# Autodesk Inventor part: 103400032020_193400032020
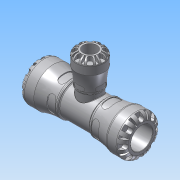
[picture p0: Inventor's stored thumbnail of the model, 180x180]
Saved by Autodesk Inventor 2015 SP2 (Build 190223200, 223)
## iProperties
Created: 2016-12
Part Number: 103400032020_193400032020
Material: PVC-Piping
Description: PLASSON REDUCING TEE 32X20X32 SERIES 1
Document SubType Name: Modeling
Designer: KIM
Mass: 664.223 g
Surface Area: 733.008 cm^2
Volume: 474.445 cm^3
Density: 1.4 g/cm^3
Appearance: Smooth - White
Author: KIM
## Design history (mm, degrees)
derived "1034.ipt"
feature "Solid1::1034.ipt"
tag "TaggingFeature1"
body "Solid1"
other parameters: "d9" = 9, "d11" = 58, "d230" = 41, "d231" = 25, "d232" = 8, "d1" = 22.68, "d2" = 32, "d4" = 58, "d8" = 49.3, "d13" = 7.2, "d14" = 7.2, "d15" = 0, "d17" = 360 deg, "d19" = 8 deg, "d20" = 0.64, "d21" = 0.64, "d22" = 8 deg, "d24" = 0, "d26" = 360 deg, "d33" = 5.8, "d43" = 45.24, "d51" = 0.58, "d54" = 11.2, "d55" = 7.04, "d57" = 14.112, "d58" = 0, "d74" = 0, "d77" = 2.66667, "d78" = 54, "d79" = 45.24, "d80" = 152, "d82" = 0.64, "d115" = 360 deg, "d139" = 7.2, "d140" = 0, "d142" = 360 deg, "d207" = 90 deg, "d209" = 19.32, "d211" = 25, "d212" = 41, "d213" = 34.85, "d215" = 31.98, "d216" = 1.66667, "d217" = 46, "d225" = 75, "d226" = 46, "d228" = 9.52, "d229" = 6.4, "d233" = 6.4, "d234" = 0, "d236" = 360 deg, "d238" = 8 deg, "d239" = 8 deg, "d240" = 0.64, "d241" = 0.64, "d243" = 0, "d245" = 360 deg, "d247" = 1.16, "d248" = 3.24, "d249" = 2.76, "d250" = 5.95, "d252" = 7, "d253" = 4.6, "d254" = 14.112, "d255" = 0, "d257" = 360 deg, "d259" = 0.64, "d261" = 0, "d262" = 1.16, "d264" = 0, "d266" = 0, "d267" = 0.58, "d_" = 32, "E_" = 58, "l_" = 54, "A_" = 75, "H_" = 152, "E_1" = 41, "l_1" = 46
